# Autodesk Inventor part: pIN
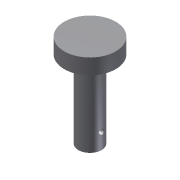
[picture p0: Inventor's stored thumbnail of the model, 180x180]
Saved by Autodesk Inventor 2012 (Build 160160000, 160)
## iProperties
Created: 2012-02
Part Number: pIN
Material: Default
Document SubType Name: Modeling
Designer: cadcim
Density: 1 g/cm^3
Author: cadcim
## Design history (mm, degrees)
sketch "Sketch1"
  geometry: C1 r 5 at (0, 0); 1 further point
  constraints: 1 centre point, 1 coincident
  dimensions: "d0" = 10 diameter of C1
extrude "Extrusion1" new body sketch "Sketch1" distance "d1" = 3; taper "d2" = 0 deg
sketch "Sketch2"
  geometry: C1 r 2.25 at (0, 0); 1 further point
  constraints: 1 centre point, 1 coincident
  dimensions: "d3" = 4.5 diameter of C1
extrude "Extrusion2" join sketch "Sketch2" distance "d4" = 15; taper "d5" = 0 deg
sketch "Sketch3"
  geometry: C1 r 0.5 at (0, -11.958); 1 further point
  constraints: 1 centre point
  dimensions: "d6" = 1 diameter of C1
extrude "Extrusion3" cut sketch "Sketch3" stored distance "d7" = 15; taper "d8" = 0 deg
body "Solid1"
